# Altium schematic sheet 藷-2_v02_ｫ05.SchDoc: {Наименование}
size 420 x 297 mm; DrawnBy: Булычев; Engineer: {Инженер}; DocumentNumber: СИЭТ 21.02.110.000 Э3; SheetNumber: 5; SheetTotal: 6; Title1str: Плата управления; PageSetup: Record=PageOptions|CenterHorizontal=False|CenterVertical=False|PrintScale=0.95|XCorrection=1.00|YCorrection=1.00|PrintKind=2|BorderSize=5000000|LeftOffset=300|BottomOffset=0|Orientation=2|PaperLength=4200|PaperWidth=2970|Scale=100|PaperSource=15|PrintQuality=-1|MediaType=1|DitherType=10|PaperKind=ISO A3|PrintScaleMode=1; Title2str: (ПУ-2); EngineerName: {Инженер}; DocumentType: Схема электрическая принципиальная; DocumentType1str: {Документ}; DocumentType2str: {Документ}
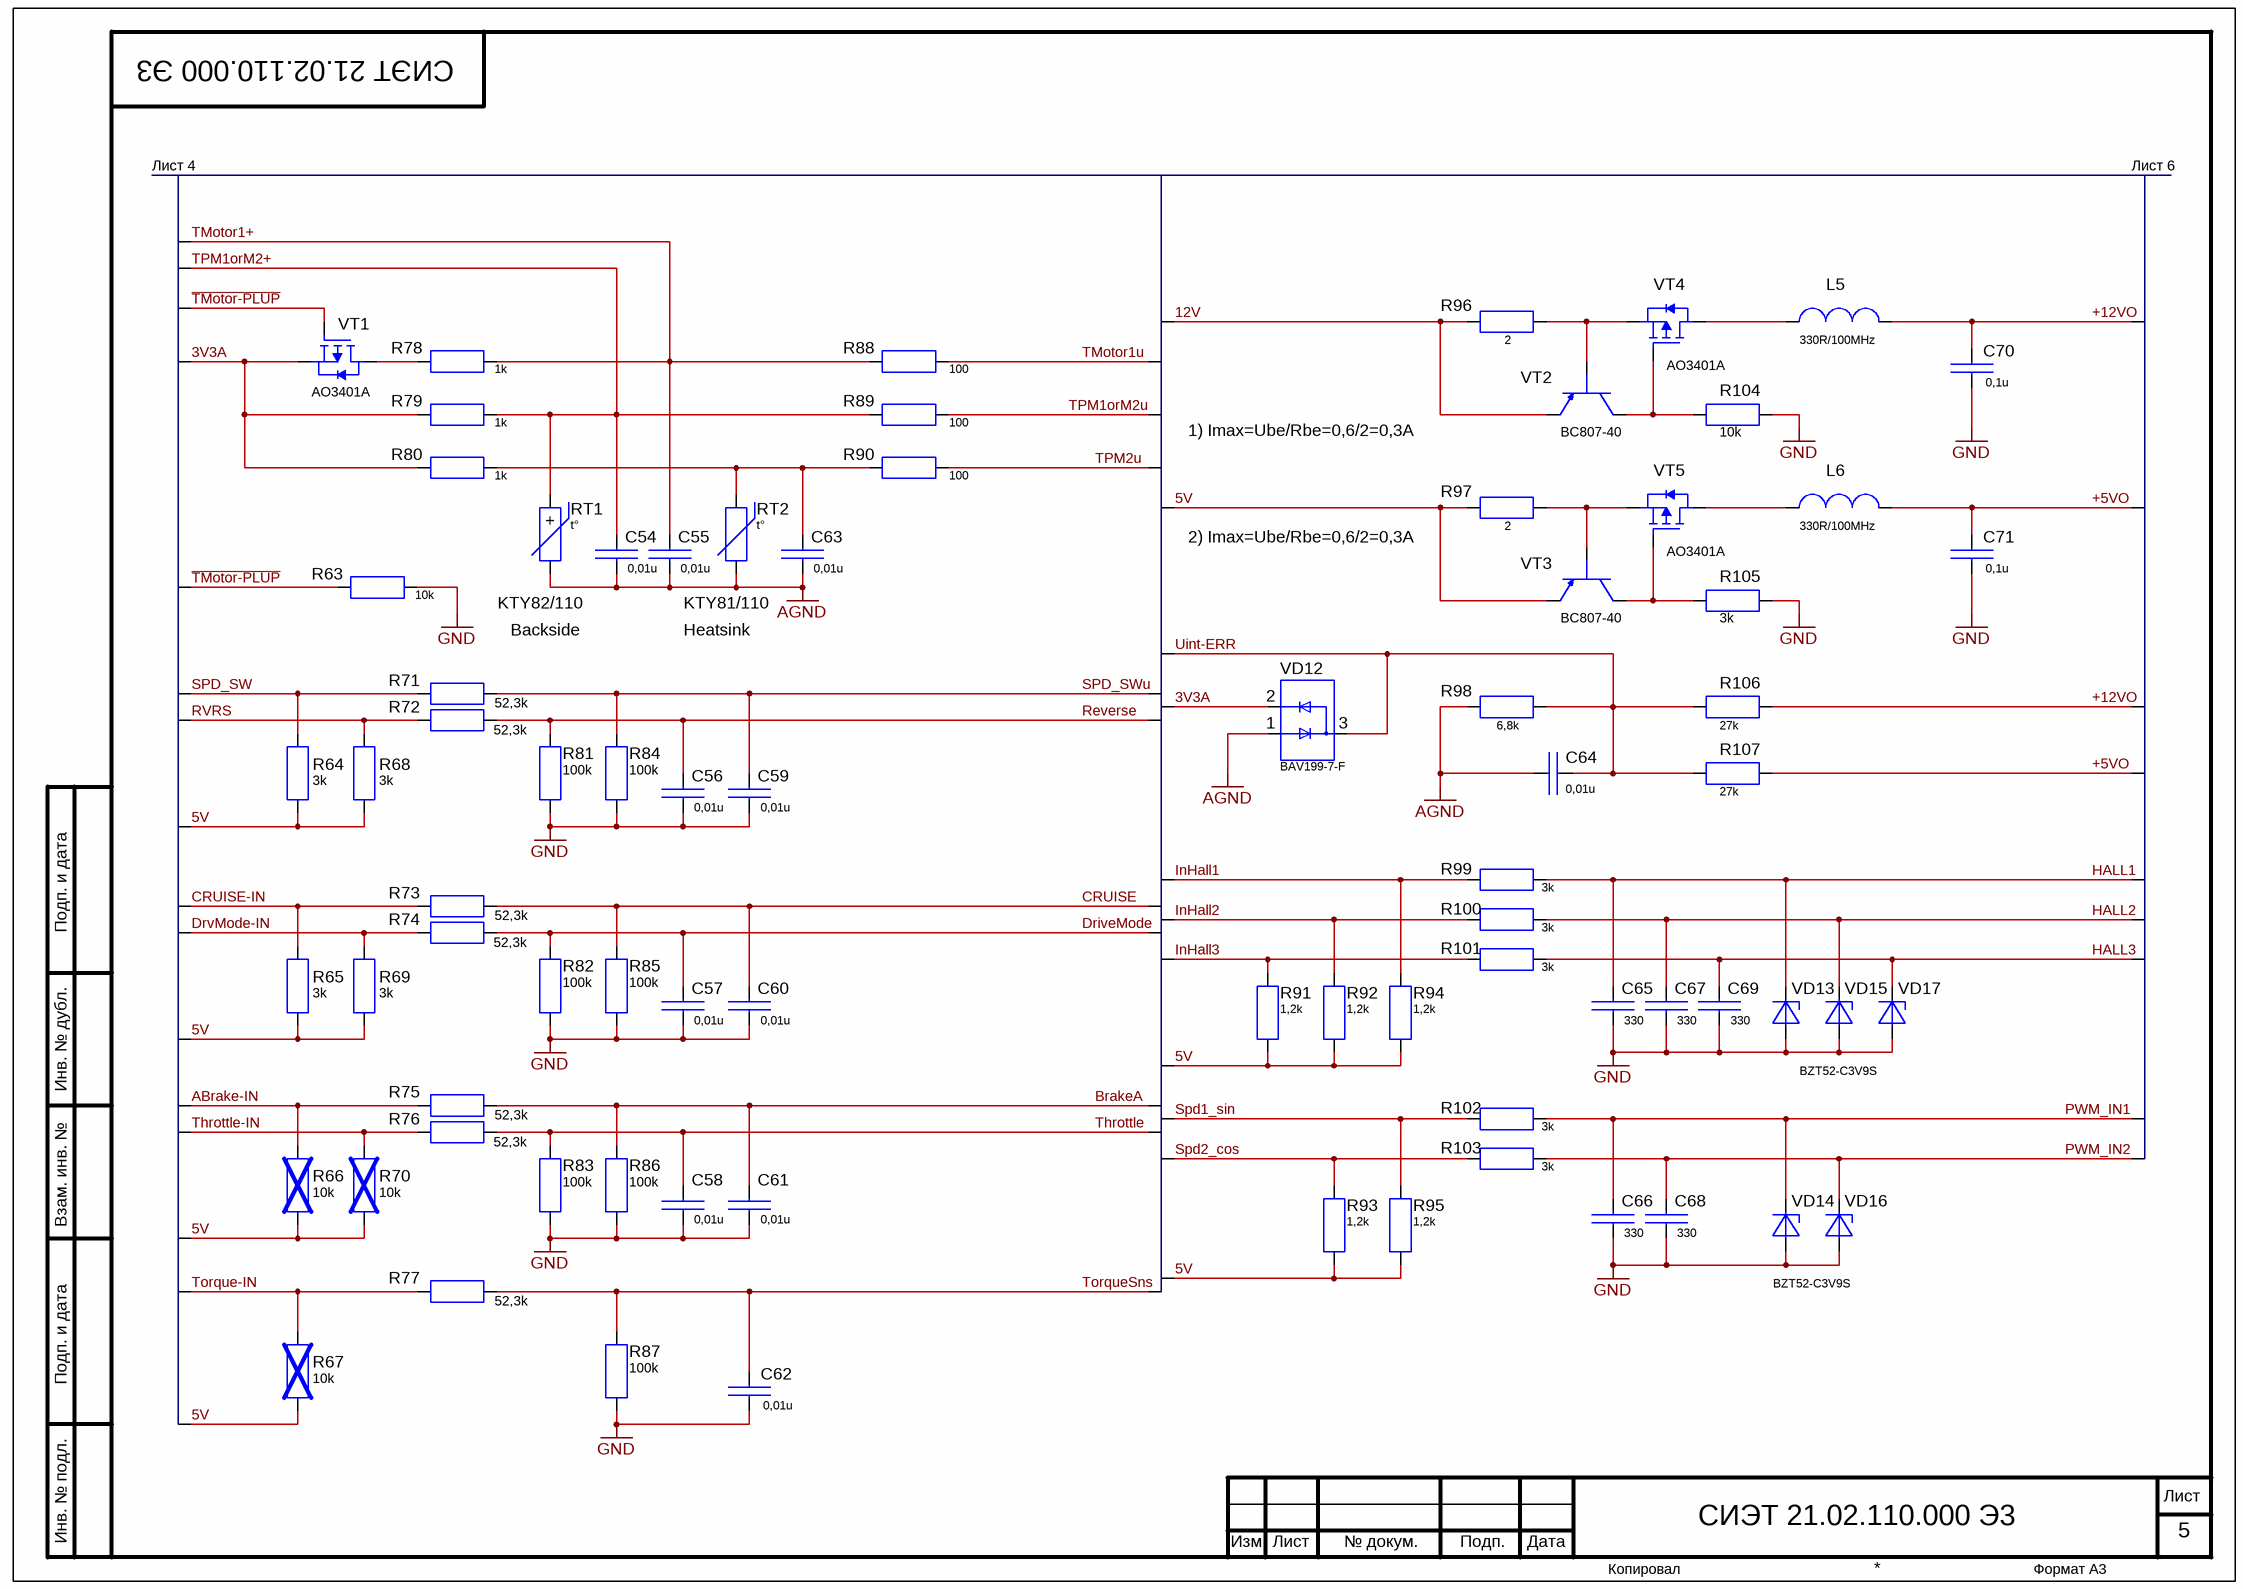
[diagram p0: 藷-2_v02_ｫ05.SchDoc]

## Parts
C54  value 0,01u  [0603]  (hidden comment: CL10B103KB8NNNC)
C55  value 0,01u  [0603]  (hidden comment: CL10B103KB8NNNC)
C56  value 0,01u  [0603]  (hidden comment: CL10B103KB8NNNC)
C57  value 0,01u  [0603]  (hidden comment: CL10B103KB8NNNC)
C58  value 0,01u  [0603]  (hidden comment: CL10B103KB8NNNC)
C59  value 0,01u  [0603]  (hidden comment: CL10B103KB8NNNC)
C60  value 0,01u  [0603]  (hidden comment: CL10B103KB8NNNC)
C61  value 0,01u  [0603]  (hidden comment: CL10B103KB8NNNC)
C62  value 0,01u  [0603]  (hidden comment: CL10B103KB8NNNC)
C63  value 0,01u  [0603]  (hidden comment: CL10B103KB8NNNC)
C64  value 0,01u  [0603]  (hidden comment: CL10B103KB8NNNC)
C65  value 330  [0603]  (hidden comment: CL10C331JB8NNNC)
C66  value 330  [0603]  (hidden comment: CL10C331JB8NNNC)
C67  value 330  [0603]  (hidden comment: CL10C331JB8NNNC)
C68  value 330  [0603]  (hidden comment: CL10C331JB8NNNC)
C69  value 330  [0603]  (hidden comment: CL10C331JB8NNNC)
C70  value 0,1u  [0603]  (hidden comment: CL10B104KB8NNNC)
C71  value 0,1u  [0603]  (hidden comment: CL10B104KB8NNNC)
L5  Impedance@100МHz: 330R/100MHz  [BLM18]  (hidden comment: BLM18PG331SN1D)
L6  Impedance@100МHz: 330R/100MHz  [BLM18]  (hidden comment: BLM18PG331SN1D)
R63  value 10k  [RC0603]  (hidden comment: RC0603FR-0710KL)
R64  value 3k  [RC0603]  (hidden comment: RC0603FR-073KL)
R65  value 3k  [RC0603]  (hidden comment: RC0603FR-073KL)
R66  value 10k  [RC0603]  (hidden comment: RC0603FR-0710KL)
R67  value 10k  [RC0603]  (hidden comment: RC0603FR-0710KL)
R68  value 3k  [RC0603]  (hidden comment: RC0603FR-073KL)
R69  value 3k  [RC0603]  (hidden comment: RC0603FR-073KL)
R70  value 10k  [RC0603]  (hidden comment: RC0603FR-0710KL)
R71  value 52,3k  [RC0603]  (hidden comment: RC0603FR-0752K3L)
R72  value 52,3k  [RC0603]  (hidden comment: RC0603FR-0752K3L)
R73  value 52,3k  [RC0603]  (hidden comment: RC0603FR-0752K3L)
R74  value 52,3k  [RC0603]  (hidden comment: RC0603FR-0752K3L)
R75  value 52,3k  [RC0603]  (hidden comment: RC0603FR-0752K3L)
R76  value 52,3k  [RC0603]  (hidden comment: RC0603FR-0752K3L)
R77  value 52,3k  [RC0603]  (hidden comment: RC0603FR-0752K3L)
R78  value 1k  [RC0603]  (hidden comment: RC0603FR-071KL)
R79  value 1k  [RC0603]  (hidden comment: RC0603FR-071KL)
R80  value 1k  [RC0603]  (hidden comment: RC0603FR-071KL)
R81  value 100k  [RC0603]  (hidden comment: RC0603FR-07100KL)
R82  value 100k  [RC0603]  (hidden comment: RC0603FR-07100KL)
R83  value 100k  [RC0603]  (hidden comment: RC0603FR-07100KL)
R84  value 100k  [RC0603]  (hidden comment: RC0603FR-07100KL)
R85  value 100k  [RC0603]  (hidden comment: RC0603FR-07100KL)
R86  value 100k  [RC0603]  (hidden comment: RC0603FR-07100KL)
R87  value 100k  [RC0603]  (hidden comment: RC0603FR-07100KL)
R88  value 100  [RC0603]  (hidden comment: RC0603FR-07100RL)
R89  value 100  [RC0603]  (hidden comment: RC0603FR-07100RL)
R90  value 100  [RC0603]  (hidden comment: RC0603FR-07100RL)
R91  value 1,2k  [RC0603]  (hidden comment: RC0603FR-071K2L)
R92  value 1,2k  [RC0603]  (hidden comment: RC0603FR-071K2L)
R93  value 1,2k  [RC0603]  (hidden comment: RC0603FR-071K2L)
R94  value 1,2k  [RC0603]  (hidden comment: RC0603FR-071K2L)
R95  value 1,2k  [RC0603]  (hidden comment: RC0603FR-071K2L)
R96  value 2  [RC1206]  (hidden comment: RC1206JR-072RL)
R97  value 2  [RC1206]  (hidden comment: RC1206JR-072RL)
R98  value 6,8k  [RC0603]  (hidden comment: RC0603FR-076K8L)
R99  value 3k  [RC0603]  (hidden comment: RC0603FR-073KL)
R100  value 3k  [RC0603]  (hidden comment: RC0603FR-073KL)
R101  value 3k  [RC0603]  (hidden comment: RC0603FR-073KL)
R102  value 3k  [RC0603]  (hidden comment: RC0603FR-073KL)
R103  value 3k  [RC0603]  (hidden comment: RC0603FR-073KL)
R104  value 10k  [RC0603]  (hidden comment: RC0603FR-0710KL)
R105  value 3k  [RC0603]  (hidden comment: RC0603FR-073KL)
R106  value 27k  [RC0603]  (hidden comment: RC0603FR-0727KL)
R107  value 27k  [RC0603]  (hidden comment: RC0603FR-0727KL)
RT1  KTY82/110  value t°  [SOT23]
RT2  KTY81/110  value t°  [TO-92-2s]
VD12  BAV199-7-F  [SOT23-3]
VD13  BZT52-С3V9S  [SOD-323]
VD14  BZT52-С3V9S  [SOD-323]
VD15  BZT52-С3V9S  [SOD-323]  (value not drawn)
VD16  BZT52-С3V9S  [SOD-323]  (value not drawn)
VD17  BZT52-С3V9S  [SOD-323]  (value not drawn)
VT1  AO3401A  [SOT23]
VT2  BC807-40  [SOT-23]
VT3  BC807-40  [SOT-23]
VT4  AO3401A  [SOT23]
VT5  AO3401A  [SOT23]

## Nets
AGND: C54.1 C55.1 C63.1 C64.2 R98.1 RT1.2(K) RT2.2 VD12.1
GND: C56.1 C57.1 C58.1 C59.1 C60.1 C61.1 C62.1 C65.1 C66.1 C67.1 C68.1 C69.1 C70.1 C71.1 R63.1 R81.1 R82.1 R83.1 R84.1 R85.1 R86.1 R87.1 R104.1 R105.1 VD13.2(A) VD14.2(A) VD15.2(A) VD16.2(A) VD17.2(A)
3V3A: R79.2 R80.2 VD12.2 VT1.2(S)
5V: R64.1 R65.1 R66.1 R67.1 R68.1 R69.1 R70.1 R91.1 R92.1 R93.1 R94.1 R95.1 R97.1 VT3.2(E)
12V: R96.1 VT2.2(E)
+5VO: C71.2 L6.2 R107.2
+12VO: C70.2 L5.2 R106.2
~{TMotor-PLUP}: R63.2 VT1.1(G)
ABrake-IN: R66.2 R75.1
BrakeA: C61.2 R75.2 R86.2
CRUISE: C60.2 R73.2 R85.2
CRUISE-IN: R65.2 R73.1
DriveMode: C57.2 R74.2 R82.2
DrvMode-IN: R69.2 R74.1
HALL1: C65.2 R99.1 VD13.1(C)
HALL2: C67.2 R100.1 VD15.1(C)
HALL3: C69.2 R101.1 VD17.1(C)
InHall1: R94.2 R99.2
InHall2: R92.2 R100.2
InHall3: R91.2 R101.2
PWM_IN1: C66.2 R102.1 VD14.1(C)
PWM_IN2: C68.2 R103.1 VD16.1(C)
Reverse: C56.2 R72.2 R81.2
RVRS: R68.2 R72.1
Spd1_sin: R95.2 R102.2
Spd2_cos: R93.2 R103.2
SPD_SW: R64.2 R71.1
SPD_SWu: C59.2 R71.2 R84.2
Throttle: C58.2 R76.2 R83.2
Throttle-IN: R70.2 R76.1
TMotor1+: C55.2 R78.1 R88.2
TMotor1u: R88.1
Torque-IN: R67.2 R77.1
TorqueSns: C62.2 R77.2 R87.2
TPM1orM2+: C54.2 R79.1 R89.2 RT1.1(+)
TPM1orM2u: R89.1
TPM2u: R90.1
Uint-ERR: C64.1 R98.2 R106.1 R107.1 VD12.3
NetC63_2: C63.2 R80.1 R90.2 RT2.1
NetL5_1: L5.1 VT4.3(D)
NetL6_1: L6.1 VT5.3(D)
NetR78_2: R78.2 VT1.3(D)
NetR96_2: R96.2 VT2.1(B) VT4.2(S)
NetR97_2: R97.2 VT3.1(B) VT5.2(S)
NetR104_2: R104.2 VT2.3(C) VT4.1(G)
NetR105_2: R105.2 VT3.3(C) VT5.1(G)

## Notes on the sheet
- Лист 4
- Лист 6
- 1) Imax=Ube/Rbe=0,6/2=0,3A
- 2) Imax=Ube/Rbe=0,6/2=0,3A
- Backside
- Heatsink

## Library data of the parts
C54-C57 C59 C60 C63 C64 = CL10B103KB8NNNC: 0603 - 50V - 0,01uF; Pdf: GeneralCapacitors_12022.pdf; Voltage: 50В; Type: CL10; Tolerance: ±10%; ТКЕ: X7R
C58 C61 C62 C70 C71 = CL10B104KB8NNNC: 0603 - 50V - 0,1uF; Pdf: GeneralCapacitors_12022.pdf; Voltage: 50В; Type: CL10; Tolerance: ±10%; ТКЕ: X7R
C65-C69 = CL10B103KB8NNNC: 0603 - 50V - 0,01uF; Pdf: GeneralCapacitors_12022.pdf; Voltage: 50В; Type: CL10; Tolerance: ±5%; ТКЕ: NP0
L5 L6 = BLM18PG331SN1D: EMI Suppression Filter; Корпус: 0603; Pdf: Murata BLM.pdf; DCResistance: 0.15
R63-R95 R98-R107 = RC0603: 0603, 0.1W, Thick Film Chip Resistors; Power: 0,1 Вт; Tolerance: ±1%; Pdf: RC0603.pdf; Корпус: 0603; ТКС: ±100 ppm/K
R96 R97 = RC1206: 1206, 0.25W, Thick Film Chip Resistors; Power: 0,25 Вт; Tolerance: ±5%; Pdf: RC1206.pdf; Корпус: 1206; ТКС: ±100 ppm/K
RT1 = KTY82/110.215: Silicon temperature sensors; Pdf: KTY82_SER.pdf; КД: KTY82/110,215
RT2 = KTY81/110,112: Silicon temperature sensors; Pdf: KTY81_SER.pdf; Корпус: SOD70
VD12 = BAV199: DUAL SURFACE MOUNT LOW LEAKAGE DIODE; Pdf: BAV199.pdf; Корпус: SOT323; Замена 1: BAV199E6433HTMA1; Замена 2: BAV199LT1G; Замена 3: BAV199,215
VD13-VD17 = BZT52: SURFACE Stabilitron; Pdf: BZT52.pdf
VT1 VT4 VT5 = AO3401A: -30V P-Channel MOSFET; Pdf: AO3401A.pdf; Доп. информация: Gate - Затвор, Drain - Сток, Source - Исток; Замена 1: NTR4171PT1G; Замена 2: IRLML9303TRPBF; Замена 3: IRLML9301TRPBF; Id (at Vgs=-10V): -4.0A
VT2 VT3 = BC807-40: 45 V, 500 mA PNP general-purpose transistor; Pdf: BC807_BC807W_BC327.pdf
